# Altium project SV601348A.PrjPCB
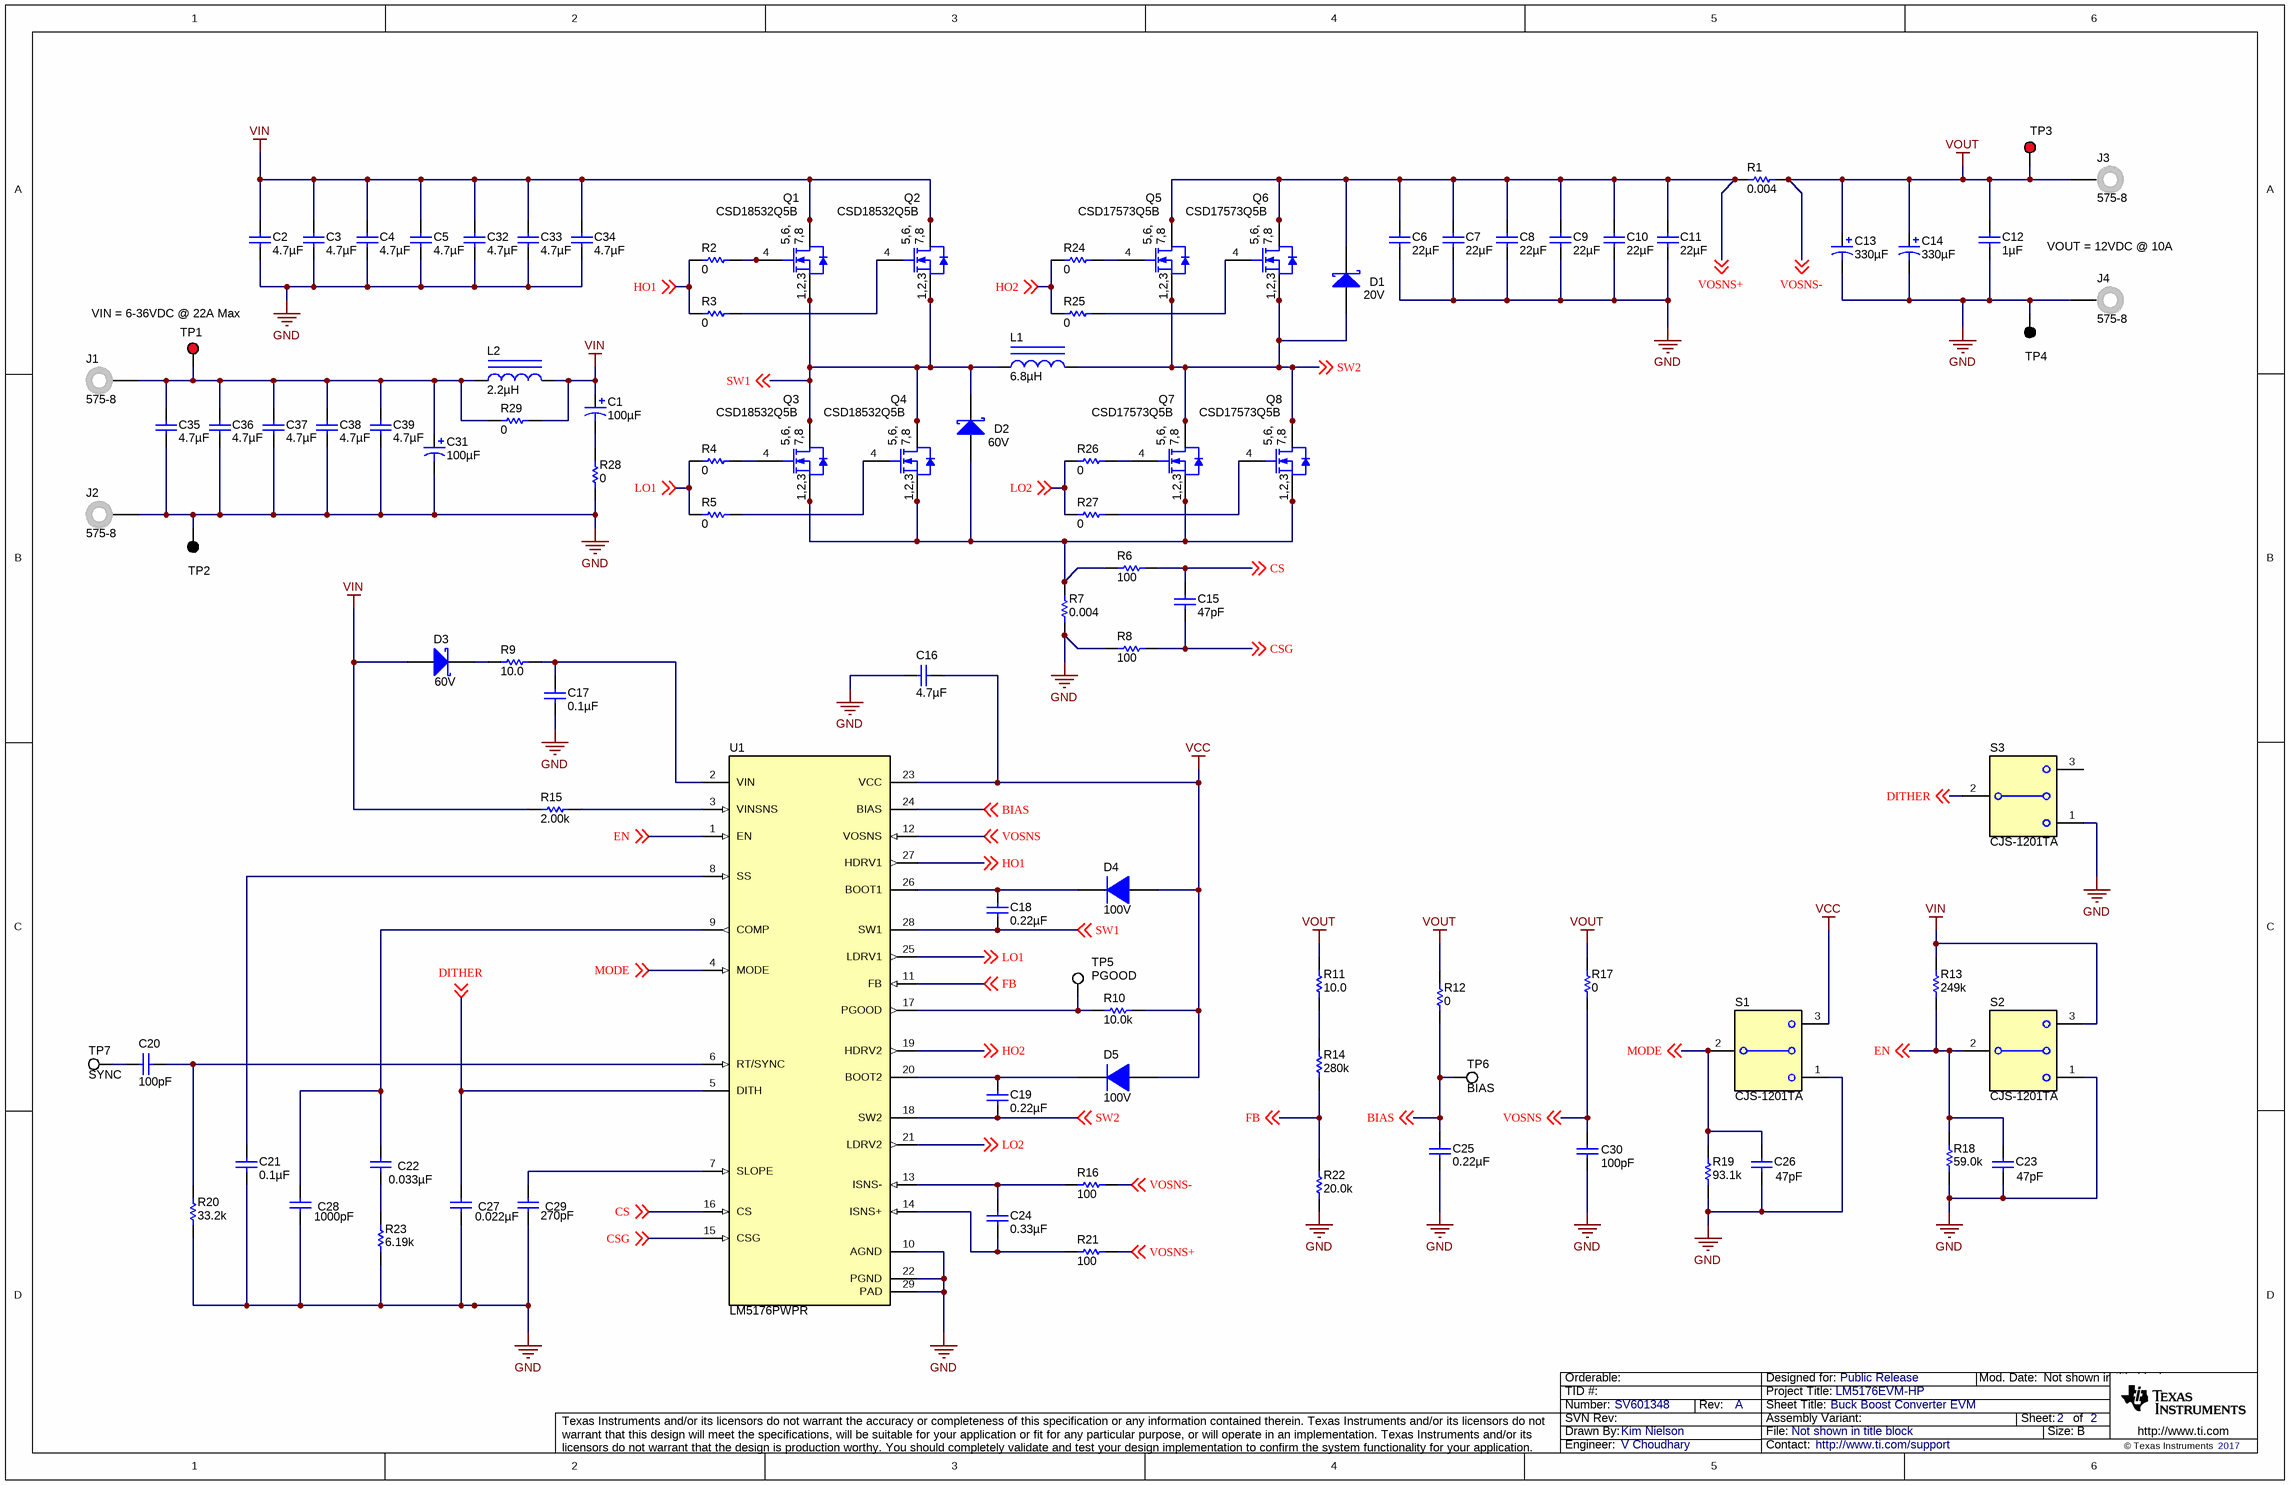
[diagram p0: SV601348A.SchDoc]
CopyrightYear: 2017; PCB_Layout: K Nielson; PCB_Rev: A; PRJ_Customer: Public Release; PRJ_Engineer: V Choudhary; PRJ_Number: SV601348; PRJ_Title: LM5176EVM-HP; SCH_Rev: A; TechSupport: http://www.ti.com/support
2 sheets, 125 parts. Net scope: global (net labels, ports and power ports of the same name join across sheets).
Board file: SV601348A.PcbDoc
Sheets:
  SV601348A.SchDoc
  SV601348A-HW.SchDoc

## Sheet SV601348A.SchDoc: Buck Boost Converter EVM
size 431 x 279 mm; Date: Not shown in title block; ApprovedBy: Not shown in title block; CheckedBy: Not shown in title block; Author: Not shown in title block; CompanyName: Not shown in title block; DrawnBy: Kim Nielson; Engineer: Neil Gutierrez; Organization: Not shown in title block; Address1: Not shown in title block; Address2: Not shown in title block; Address3: Not shown in title block; Address4: Not shown in title block; DocumentNumber: 2; Revision: Use project parameter SCH_Rev; SheetNumber: 2; SheetTotal: 2; PageSetup: Record=PageOptions¦CenterHorizontal=True¦CenterVertical=True¦PrintScale=0.62¦XCorrection=1.00¦YCorrection=1.00¦PrintKind=0¦BorderSize=5000000¦LeftOffset=0¦BottomOffset=0¦Orientation=2¦PaperLength=1000¦PaperWidth=1000¦Scale=100¦PaperSource=15¦PrintQuality=600¦MediaType=1¦DitherType=10¦PaperKind=Letter¦PrintScaleMode=1

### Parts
C1  ValueDisplayed: 100µF  [CR_1000x1270]  (hidden comment: PCR1J101MCL1GS)
C2  ValueDisplayed: 4.7µF  [1210_270]  (hidden comment: GRM32ER71K475KE14L)
C3  ValueDisplayed: 4.7µF  [1210_270]  (hidden comment: GRM32ER71K475KE14L)
C4  ValueDisplayed: 4.7µF  [1210_270]  (hidden comment: GRM32ER71K475KE14L)
C5  ValueDisplayed: 4.7µF  [1210_270]  (hidden comment: GRM32ER71K475KE14L)
C6  ValueDisplayed: 22µF  [1210_270]  (hidden comment: GRM32ER71E226KE15L)
C7  ValueDisplayed: 22µF  [1210_270]  (hidden comment: GRM32ER71E226KE15L)
C8  ValueDisplayed: 22µF  [1210_270]  (hidden comment: GRM32ER71E226KE15L)
C9  ValueDisplayed: 22µF  [1210_270]  (hidden comment: GRM32ER71E226KE15L)
C10  ValueDisplayed: 22µF  [1210_270]  (hidden comment: GRM32ER71E226KE15L)
C11  ValueDisplayed: 22µF  [1210_270]  (hidden comment: GRM32ER71E226KE15L)
C12  ValueDisplayed: 1µF  [0805_HV]  (hidden comment: GRM219R71E105KA88D)
C13  ValueDisplayed: 330µF  [SM_RADIAL_10AMM]  (hidden comment: 16SVP330M)
C14  ValueDisplayed: 330µF  [SM_RADIAL_10AMM]  (hidden comment: 16SVP330M)
C15  ValueDisplayed: 47pF  [0603L]  (hidden comment: GRM1885C1H470JA01D)
C16  ValueDisplayed: 4.7µF  [0805_HV]  (hidden comment: GRM21BR71C475KA73L)
C17  ValueDisplayed: 0.1µF  [0603L]  (hidden comment: GRM188R72A104KA35D)
C18  ValueDisplayed: 0.22µF  [0603L]  (hidden comment: GRM188R71E224KA88D)
C19  ValueDisplayed: 0.22µF  [0603L]  (hidden comment: GRM188R71E224KA88D)
C20  ValueDisplayed: 100pF  [0603L]  (hidden comment: GRM1885C2A101JA01D)
C21  ValueDisplayed: 0.1µF  [0603L]  (hidden comment: GRM188R72A104KA35D)
C22  ValueDisplayed: 0.033µF  [0603L]  (hidden comment: GRM188R71H333KA61D)
C23  47pF  [0603L]
C24  ValueDisplayed: 0.33µF  [0603L]  (hidden comment: GRM188R71C334KA01D)
C25  ValueDisplayed: 0.22µF  [0603]  (hidden comment: GRM188R71E224KA88D)
C26  47pF  [0603L]
C27  ValueDisplayed: 0.022µF  [0603L]  (hidden comment: C0603C223K5RACTU)
C28  ValueDisplayed: 1000pF  [0603L]  (hidden comment: GRM1885C2A102JA01D)
C29  ValueDisplayed: 270pF  [0603L]  (hidden comment: GRM1885C1H271JA01D)
C30  ValueDisplayed: 100pF  [0603L]  (hidden comment: GRM1885C2A101JA01D)
C31  ValueDisplayed: 100µF  [CR_1000x1270]  (hidden comment: PCR1J101MCL1GS)
C32  ValueDisplayed: 4.7µF  [1210_270]  (hidden comment: GRM32ER71K475KE14L)
C33  ValueDisplayed: 4.7µF  [1210_270]  (hidden comment: GRM32ER71K475KE14L)
C34  ValueDisplayed: 4.7µF  [1210_270]  (hidden comment: GRM32ER71K475KE14L)
C35  ValueDisplayed: 4.7µF  [1210_270]  (hidden comment: GRM32ER71K475KE14L)
C36  ValueDisplayed: 4.7µF  [1210_270]  (hidden comment: GRM32ER71K475KE14L)
C37  ValueDisplayed: 4.7µF  [1210_270]  (hidden comment: GRM32ER71K475KE14L)
C38  ValueDisplayed: 4.7µF  [1210_270]  (hidden comment: GRM32ER71K475KE14L)
C39  ValueDisplayed: 4.7µF  [1210_270]  (hidden comment: GRM32ER71K475KE14L)
D1  20V  [SMA]
D2  60V  [SMA]
D3  60V  [SOD-323F]
D4  100V  [sod-323]
D5  100V  [sod-323]
J1  575-8  [Keystone575-8]
J2  575-8  [Keystone575-8]
J3  575-8  [Keystone575-8]
J4  575-8  [Keystone575-8]
L1  ValueDisplayed: 6.8µH  [XAL1510]  (hidden comment: XAL1510-682MEB)
L2  ValueDisplayed: 2.2µH  [XAL1010]  (hidden comment: XAL1010-222MEB)
Q1  CSD18532Q5B  [DNK0008A]
Q2  CSD18532Q5B  [DNK0008A]
Q3  CSD18532Q5B  [DNK0008A]
Q4  CSD18532Q5B  [DNK0008A]
Q5  CSD17573Q5B  [DNK0008A]
Q6  CSD17573Q5B  [DNK0008A]
Q7  CSD17573Q5B  [DNK0008A]
Q8  CSD17573Q5B  [DNK0008A]
R1  ValueDisplayed: 0.004  [2512_WIDE]  (hidden comment: KRL6432E-M-R004-F-T1)
R2  value 0  [0603L]  (hidden comment: RC0603JR-070RL)
R3  value 0  [0603L]  (hidden comment: RC0603JR-070RL)
R4  value 0  [0603L]  (hidden comment: RC0603JR-070RL)
R5  value 0  [0603L]  (hidden comment: RC0603JR-070RL)
R6  value 100  [0603_HV]  (hidden comment: RC0603FR-07100RL)
R7  ValueDisplayed: 0.004  [2512_WIDE]  (hidden comment: KRL6432E-M-R004-F-T1)
R8  value 100  [0603_HV]  (hidden comment: RC0603FR-07100RL)
R9  value 10.0  [0603L]  (hidden comment: RC0603FR-0710RL)
R10  value 10.0k  [0603L]  (hidden comment: RC0603FR-0710KL)
R11  value 10.0  [0603L]  (hidden comment: RC0603FR-0710RL)
R12  value 0  [0603L]  (hidden comment: RC0603JR-070RL)
R13  value 249k  [0603L]  (hidden comment: RC0603FR-07249KL)
R14  value 280k  [0603L]  (hidden comment: RC0603FR-07280KL)
R15  ValueDisplayed: 2.00k  [0603]  (hidden comment: CRCW06032K00FKEA)
R16  100  [0603L]
R17  value 0  [0603L]  (hidden comment: RC0603JR-070RL)
R18  value 59.0k  [0603L]  (hidden comment: RC0603FR-0759KL)
R19  ValueDisplayed: 93.1k  [0603L]  (hidden comment: RC0603FR-0793K1L)
R20  ValueDisplayed: 33.2k  [0603L]  (hidden comment: CRCW060333K2FKEA)
R21  100  [0603L]
R22  value 20.0k  [0603L]  (hidden comment: RC0603FR-0720KL)
R23  ValueDisplayed: 6.19k  [0603L]  (hidden comment: CRCW06036K19FKEA)
R24  value 0  [0603L]  (hidden comment: RC0603JR-070RL)
R25  value 0  [0603L]  (hidden comment: RC0603JR-070RL)
R26  value 0  [0603L]  (hidden comment: RC0603JR-070RL)
R27  value 0  [0603L]  (hidden comment: RC0603JR-070RL)
R28  ValueDisplayed: 0  [1206]  (hidden comment: CRCW12060000Z0EA)
R29  ValueDisplayed: 0  [2512_WIDE_VISHAY]  (hidden comment: RCL12250000Z0EG)
S1  CJS-1201TA  [SW_CJS_1201A]
S2  CJS-1201TA  [SW_CJS_1201A]
S3  CJS-1201TA  [SW_CJS_1201A]
TP1  5005  [Keystone5005]  (value not drawn)
TP2  5006  [Keystone5006]  (value not drawn)
TP3  5005  [Keystone5005]  (value not drawn)
TP4  5006  [Keystone5006]  (value not drawn)
TP5  PGOOD  [Keystone5007]
TP6  BIAS  [Keystone5007]
TP7  SYNC  [Keystone5007]
U1  LM5176PWPR  [PWP0028C_N]

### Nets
GND: C2.2 C3.2 C4.2 C5.2 C6.2 C7.2 C8.2 C9.2 C10.2 C11.2 C12.2 C13.2(-) C14.2(-) C16.1 C17.2 C21.2 C23.2 C25.2 C26.2 C27.2 C28.2 C29.2 C30.2 C31.2(-) C32.2 C33.2 C34.2 C35.2 C36.2 C37.2 C38.2 C39.2 J2.1 J4.1 R7.1 R8.2 R18.1 R19.1 R20.1 R22.1 R23.1 R28.1 S1.1 S2.1 S3.1 TP2.1 TP4.1 U1.10(AGND) U1.22(PGND) U1.29(PAD)
VCC: C16.2 D4.2(A) D5.2(A) R10.2 S1.3 U1.23(VCC)
VIN: C1.1(+) C2.1 C3.1 C4.1 C5.1 C32.1 C33.1 C34.1 D3.2(A) L2.2 Q1.5(D) Q1.6(D) Q1.7(D) Q1.8(D) Q1.9(D) Q2.5(D) Q2.6(D) Q2.7(D) Q2.8(D) Q2.9(D) R13.2 R15.2 R29.2 S2.3
VOUT: C12.1 C13.1(+) C14.1(+) J3.1 R1.2 R11.1 R12.1 R16.2 R17.1 TP3.1 ; off-sheet VOSNS-  [also labelled VOSNS-]
BIAS: C25.1 R12.2 TP6.1 U1.24(BIAS) ; off-sheet BIAS
CS: C15.1 R6.1 U1.16(CS) ; off-sheet CS
CSG: C15.2 R8.1 U1.15(CSG) ; off-sheet CSG
DITHER: C27.1 S3.2(COM) U1.5(DITH) ; off-sheet DITHER
EN: C23.1 R13.1 R18.2 S2.2(COM) U1.1(EN) ; off-sheet EN
FB: R14.1 R22.2 U1.11(FB) ; off-sheet FB
HO1: R2.2 R3.2 U1.27(HDRV1) ; off-sheet HO1
HO2: R24.2 R25.2 U1.19(HDRV2) ; off-sheet HO2
LO1: R4.2 R5.2 U1.25(LDRV1) ; off-sheet LO1
LO2: R26.2 R27.2 U1.21(LDRV2) ; off-sheet LO2
MODE: C26.1 R19.2 S1.2(COM) U1.4(MODE) ; off-sheet MODE
SW1: C18.1 D2.1(K) L1.1 Q1.1(S) Q1.2(S) Q1.3(S) Q2.1(S) Q2.2(S) Q2.3(S) Q3.5(D) Q3.6(D) Q3.7(D) Q3.8(D) Q3.9(D) Q4.5(D) Q4.6(D) Q4.7(D) Q4.8(D) Q4.9(D) U1.28(SW1) ; off-sheet SW1
SW2: C19.2 D1.2(A) L1.2 Q5.1(S) Q5.2(S) Q5.3(S) Q6.1(S) Q6.2(S) Q6.3(S) Q7.5(D) Q7.6(D) Q7.7(D) Q7.8(D) Q7.9(D) Q8.5(D) Q8.6(D) Q8.7(D) Q8.8(D) Q8.9(D) U1.18(SW2) ; off-sheet SW2
VOSNS: C30.1 R17.2 U1.12(VOSNS) ; off-sheet VOSNS
VOSNS+: C6.1 C7.1 C8.1 C9.1 C10.1 C11.1 D1.1(K) Q5.5(D) Q5.6(D) Q5.7(D) Q5.8(D) Q5.9(D) Q6.5(D) Q6.6(D) Q6.7(D) Q6.8(D) Q6.9(D) R1.1 R21.2 ; off-sheet VOSNS+
NetC1_2: C1.2(-) R28.2
NetC17_1: C17.1 R9.1 U1.2(VIN)
NetC18_2: C18.2 D4.1(K) U1.26(BOOT1)
NetC19_1: C19.1 D5.1(K) U1.20(BOOT2)
NetC20_1: C20.1 TP7.1
NetC20_2: C20.2 R20.2 U1.6(RT/SYNC)
NetC21_1: C21.1 U1.8(SS)
NetC22_1: C22.1 C28.1 U1.9(COMP)
NetC22_2: C22.2 R23.2
NetC24_1: C24.1 R16.1 U1.13(ISNS-)
NetC24_2: C24.2 R21.1 U1.14(ISNS+)
NetC29_1: C29.1 U1.7(SLOPE)
NetC31_1: C31.1(+) C35.1 C36.1 C37.1 C38.1 C39.1 J1.1 L2.1 R29.1 TP1.1
NetD2_2: D2.2(A) Q3.1(S) Q3.2(S) Q3.3(S) Q4.1(S) Q4.2(S) Q4.3(S) Q7.1(S) Q7.2(S) Q7.3(S) Q8.1(S) Q8.2(S) Q8.3(S) R6.2 R7.2
NetD3_1: D3.1(K) R9.2
NetQ1_4: Q1.4(G) R2.1
NetQ2_4: Q2.4(G) R3.1
NetQ3_4: Q3.4(G) R4.1
NetQ4_4: Q4.4(G) R5.1
NetQ5_4: Q5.4(G) R24.1
NetQ6_4: Q6.4(G) R25.1
NetQ7_4: Q7.4(G) R26.1
NetQ8_4: Q8.4(G) R27.1
NetR10_1: R10.1 TP5.1 U1.17(PGOOD)
NetR11_2: R11.2 R14.2
NetR15_1: R15.1 U1.3(VINSNS)

Not connected (* = marked no-connect by the designer): S3 3

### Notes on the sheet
- VOUT = 12VDC @ 10A
- (near TP1) VIN = 6-36VDC @ 22A Max

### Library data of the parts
C1 C31 = PCR1J101MCL1GS: CAP, Aluminum Polymer, 100 µF, 63 V, +/- 20%, 0.024 ohm, SMD, 2-Leads, Dia 10.5mm, Pin Spacing 8mm SMD; Manufacturer: Nichicon; Polarized: Y; CompType: Capacitor; Value: 100uF; U/M: EA; Cap_F: 0.0001; Tolerance_%: 20; VDC_V: 63; Value2: 63V; ESR_ohm: 0.024; IRMS_A: 3; TaMin_C: -55; TaMax_C: 125; Cap_Case: 10x12.7mm; AEC Category: Q200; AEC Qualified: N
C2-C5 C32-C39 = GRM32ER71K475KE14L: CAP, CERM, 4.7 µF, 80 V, +/- 10%, X7R, 1210; Manufacturer: MuRata; CompType: Capacitor; Value: 4.7uF; U/M: EA; Tolerance_%: 10; VDC_V: 80; Polarized: N; Cap_F: 0.0000047; Value1: Unknown; Value2: 80V; TaMin_C: -55; TaMax_C: 125; Cap_Case: 1210; SizeArea_mm2: 8; SizeAreaWB_mm2: 14.7; SizeX_mm: 3.2; SizeY_mm: 2.5; SizeZ_mm: 2.7; AEC Category: Q200
C6-C11 = GRM32ER71E226KE15L: CAP, CERM, 22 µF, 25 V, +/- 10%, X7R, 1210; Manufacturer: MuRata; CompType: Capacitor; Value: 22uF; U/M: EA; Tolerance_%: 10; VDC_V: 25; Polarized: N; Cap_F: 0.000022; Value1: Unknown; Value2: 25V; TaMin_C: -55; TaMax_C: 125; Cap_Case: 1210; SizeArea_mm2: 8; SizeAreaWB_mm2: 14.7; SizeX_mm: 3.2; SizeY_mm: 2.5; SizeZ_mm: 2.7; AEC Category: Q200
C12 = GRM219R71E105KA88D: CAP, CERM, 1 µF, 25 V, +/- 10%, X7R, 0805; Manufacturer: MuRata; Polarized: N; CompType: Capacitor; Value: 1uF; U/M: EA; Cap_F: 0.000001; Tolerance_%: 10; Value1: Unknown; VDC_V: 25; Value2: 25V; TaMin_C: -55; TaMax_C: 125; Cap_Case: 0805
C13 C14 = 16SVP330M: CAP, OS-CON, 330 µF, 16 V, +/- 20%, 0.016 ohm, 10x10.3 SMD; Manufacturer: Sanyo; CompType: Capacitor; Value: 330uF; U/M: EA; Tolerance_%: 20; VDC_V: 16; ESR_ohm: 0.016; Polarized: Y; Cap_F: 0.00033; Value2: 16V; IRMS_A: 4.72; TaMin_C: -55; TaMax_C: 105; Cap_Case: 10.3x10.3x12.6
C15 C23 C26 = GRM1885C1H470JA01D: CAP, CERM, 47pF, 50V, +/-5%, C0G/NP0, 0603; Manufacturer: MuRata; Polarized: N; CompType: Capacitor; U/M: EA; Cap_F: 0.000000000047; Tolerance_%: 5; Value1: Unknown; VDC_V: 50; TaMin_C: -55; TaMax_C: 125; Cap_Case: 0603
C16 = GRM21BR71C475KA73L: CAP, CERM, 4.7 µF, 16 V, +/- 10%, X7R, 0805; Manufacturer: MuRata; Polarized: N; CompType: Capacitor; Value: 4.7uF; U/M: EA; Cap_F: 0.0000047; Tolerance_%: 10; ESR_ohm: 0.006; Value1: 0.006 ohm; VDC_V: 16; Value2: 16V; TaMin_C: -55; TaMax_C: 125; Cap_Case: 0805
C17 C21 = GRM188R72A104KA35D: CAP, CERM, 0.1uF, 100V, +/-10%, X7R, 0603; Manufacturer: MuRata; Polarized: N; CompType: Capacitor; U/M: EA; Cap_F: 0.0000001; Tolerance_%: 10; Value1: Unknown; VDC_V: 100; TaMin_C: -55; TaMax_C: 125; Cap_Case: 0603
C18 C19 = GRM188R71E224KA88D: CAP, CERM, 0.22 µF, 25 V, +/- 10%, X7R, 0603; Manufacturer: MuRata; Polarized: N; CompType: Capacitor; Value: 0.22uF; U/M: EA; Cap_F: 0.00000022; Tolerance_%: 10; Value1: Unknown; VDC_V: 25; Value2: 25V; TaMin_C: -55; TaMax_C: 125; Cap_Case: 0603
C20 C30 = GRM1885C2A101JA01D: CAP, CERM, 100pF, 100V, +/-5%, C0G/NP0, 0603; Manufacturer: MuRata; Polarized: N; CompType: Capacitor; U/M: EA; Cap_F: 0.0000000001; Tolerance_%: 5; Value1: Unknown; VDC_V: 100; TaMin_C: -55; TaMax_C: 125; Cap_Case: 0603
C22 = GRM188R71H333KA61D: CAP, CERM, 0.033 µF, 50 V, +/- 10%, X7R, 0603; Manufacturer: MuRata; Polarized: N; CompType: Capacitor; Value: 0.033uF; U/M: EA; Cap_F: 0.000000033; Tolerance_%: 10; Value1: Unknown; VDC_V: 50; Value2: 50V; TaMin_C: -55; TaMax_C: 125; Cap_Case: 0603; SizeArea_mm2: 1.28; SizeAreaWB_mm2: 4.68; SizeX_mm: 1.6; SizeY_mm: 0.8; SizeZ_mm: 1; AEC Category: Q200
C24 = GRM188R71C334KA01D: CAP, CERM, 0.33 µF, 16 V, +/- 10%, X7R, 0603; Manufacturer: MuRata; Polarized: N; CompType: Capacitor; Value: 0.33uF; U/M: EA; Cap_F: 0.00000033; Tolerance_%: 10; Value1: Unknown; VDC_V: 16; Value2: 16V; TaMin_C: -55; TaMax_C: 125; Cap_Case: 0603
C25 = GRM188R71E224KA88D: CAP, CERM, 0.22 µF, 25 V, +/- 10%, X7R, 0603; Manufacturer: MuRata; Polarized: N; CompType: Capacitor; Value: 0.22uF; U/M: EA; Cap_F: 0.00000022; Tolerance_%: 10; Value1: Unknown; VDC_V: 25; Value2: 25V; TaMin_C: -55; TaMax_C: 125
C27 = C0603C223K5RACTU: CAP, CERM, 0.022uF, 50V, +/-10%, X7R, 0603; Manufacturer: Kemet; Polarized: N; CompType: Capacitor; U/M: EA; Cap_F: 0.000000022; Tolerance_%: 10; Value1: Unknown; VDC_V: 50; TaMin_C: -55; TaMax_C: 125; Cap_Case: 0603
C28 = GRM1885C2A102JA01D: CAP, CERM, 1000 pF, 100 V, +/- 5%, C0G/NP0, 0603; Manufacturer: MuRata; Polarized: N; CompType: Capacitor; Value: 1000pF; U/M: EA; Cap_F: 0.000000001; Tolerance_%: 5; Value1: Unknown; VDC_V: 100; Value2: 100V; TaMin_C: -55; TaMax_C: 125; Cap_Case: 0603; SizeArea_mm2: 1.28; SizeAreaWB_mm2: 4.68; SizeX_mm: 1.6; SizeY_mm: 0.8; SizeZ_mm: 1; AEC Category: Q200
C29 = GRM1885C1H271JA01D: CAP, CERM, 270 pF, 50 V, +/- 5%, C0G/NP0, 0603; Manufacturer: MuRata; Polarized: N; CompType: Capacitor; Value: 270pF; U/M: EA; Cap_F: 0.00000000027; Tolerance_%: 5; Value1: Unknown; VDC_V: 50; Value2: 50V; TaMin_C: -55; TaMax_C: 125; Cap_Case: 0603; SizeArea_mm2: 1.28; SizeAreaWB_mm2: 4.68; SizeX_mm: 1.6; SizeY_mm: 0.8; SizeZ_mm: 1; AEC Category: Q200
D1 = RSX501L-20TE25: Diode, Schottky, 20 V, 5 A, SMA; Manufacturer: Rohm; U/M: EA; Vf_V: 0.39; Value1: 5A; Value2: 0.39V; Io_A: 5; Vr_V: 20; TJmax_C: 125
D2 = RB050L-60TE25: Diode, Schottky, 60 V, 3 A, SMA; Manufacturer: Rohm; U/M: EA; Vf_V: 0.56; Value1: 3A; Value2: 0.56V; Io_A: 3; Vr_V: 60; TJmax_C: 150
D3 = PMEG6010CEJ,115: Diode, Schottky, 60 V, 1 A, SOD-323F; Manufacturer: NXP Semiconductor; U/M: EA; Vf_V: 0.66; Value1: 1A; Value2: 0.66V; Io_A: 1; Vr_V: 60; TJmax_C: 150
D4 D5 = BAS316,115: Diode, Ultrafast, 100V, 0.25A, SOD-323; Manufacturer: NXP Semiconductor; U/M: EA; Vr_V: 100; Io_A: 0.25; Vf_V: 1.4; Value2: 1.4V; TJmax_C: 150
J1-J4 = 575-8: Standard Banana Jack, Uninsulated, 8.9mm; Manufacturer: Keystone; CompType: Connector
L1 = XAL1510-682MEB: Inductor, Shielded, Composite, 6.8 µH, 26 A, 0.00417 ohm, SMD; Manufacturer: Coilcraft; Value: 6.8uH; Ind_H: 6.8E-6; Imax_A: 26; Irms: 26A @ 40C rise; Isat: 36A @ 30% inductance drop; Value2: 26A; SizeAreaWB_mm2: 320.16; SizeArea_mm2: 252.56; SizeX_mm: 16.4; SizeY_mm: 15.4; SizeZ_mm: 10; AEC Category: Q200
L2 = XAL1010-222MEB: Inductor, Shielded, Composite, 2.2 µH, 32 A, 0.00255 ohm, SMD; Manufacturer: Coilcraft; Value: 2.2uH; Ind_H: 2.2E-6; Imax_A: 32; Irms: 32A @ 40C rise; Isat: 34A @ 30% inductance drop; Value2: 32A; SizeAreaWB_mm2: 159.6; SizeArea_mm2: 113; SizeX_mm: 11.3; SizeY_mm: 10; AEC Category: Q200
Q1-Q4 = CSD18532Q5B: MOSFET, N-CH, 60 V, 172 A, DNK0008A (VSON-CLIP-8); Manufacturer: Texas Instruments; Alternate Manufacturer: None; U/M: EA; ChType: N; Value: 60V; VdsMax_V: 60; Value1: 3.3 ohm; Rdson45_ohm: 3.3; Value2: 27 nC; QgTyp_nC: 27; Vgs_V: 1.6; IdsMax_A: 172; SizeAreaWB_mm2: 56; SizeArea_mm2: 30; SizeX_mm: 6; SizeY_mm: 5; SizeZ_mm: 1; AEC Category: Q101
Q5-Q8 = CSD17573Q5B: MOSFET, N-CH, 30 V, 100 A, DNK0008A (VSON-CLIP-8); Manufacturer: Texas Instruments; Alternate Manufacturer: None; U/M: EA; ChType: N; Value: 30V; VdsMax_V: 30; Value1: 0.00145 ohm; Rdson45_ohm: 0.00145; Value2: 49 nC; QgTyp_nC: 49; Vgs_V: 20; IdsMax_A: 100; SizeAreaWB_mm2: 56; SizeX_mm: 6; SizeY_mm: 5; SizeZ_mm: 1; AEC Category: Q101
R1 = KRL6432E-M-R004-F-T1: RES, 0.004, 1%, 3 W, 2512 WIDE; Manufacturer: Susumu Co Ltd; CompType: Resistor; U/M: EA; Value: 0.004; Power_W: 3; Tolerance_%: 1; TempCo: 50 ppm/C; Value_Code: 4L000; Value2: 3W; SizeArea_mm2: 20.16; SizeAreaWB_mm2: 43.16; SizeX_mm: 3.2; SizeY_mm: 6.3; SizeZ_mm: 0.7; AEC Category: Q200
R2-R5 R12 R17 R24-R27 = RC0603JR-070RL: RES, 0 ohm, 5%, 0.1W, 0603; Manufacturer: Yageo America; CompType: Resistor; Value_Code: 0000; Tolerance_%: 5; Power_W: 0.1; VDC_V: 50; TempCo: 200 ppm/C; EIA_Code: E24; U/M: EA
R6 R8 R16 R21 = RC0603FR-07100RL: RES, 100 ohm, 1%, 0.1W, 0603; Manufacturer: Yageo America; CompType: Resistor; Value_Code: 100R; Tolerance_%: 1; Power_W: 0.1; VDC_V: 150; TempCo: 200 ppm/C; EIA_Code: E96; U/M: EA
R7 = KRL6432E-M-R004-F-T1: RES, 0.004, 1%, 3 W, 2512 WIDE; Manufacturer: Susumu Co Ltd; CompType: Resistor; Value: 0.004; Tolerance_%: 1; Power_W: 3; TempCo: 50 ppm/C; U/M: EA; Value_Code: 4L000; Value2: 3W; SizeArea_mm2: 20.16; SizeAreaWB_mm2: 43.16; SizeX_mm: 3.2; SizeY_mm: 6.3; SizeZ_mm: 0.7; AEC Category: Q200
R9 R11 = RC0603FR-0710RL: RES, 10.0 ohm, 1%, 0.1W, 0603; Manufacturer: Yageo America; CompType: Resistor; Res_ohm: 10; Value_Code: 10R0; Tolerance_%: 1; Power_W: 0.1; VDC_V: 150; TempCo: 200 ppm/C; EIA_Code: E96; U/M: EA
R10 = RC0603FR-0710KL: RES, 10.0k ohm, 1%, 0.1W, 0603; Manufacturer: Yageo America; CompType: Resistor; Res_ohm: 10000; Value_Code: 10k0; Tolerance_%: 1; Power_W: 0.1; VDC_V: 150; TempCo: 200 ppm/C; EIA_Code: E96; U/M: EA
R13 = RC0603FR-07249KL: RES, 249k ohm, 1%, 0.1W, 0603; Manufacturer: Yageo America; CompType: Resistor; Res_ohm: 249000; Tolerance_%: 1; Power_W: 0.1; VDC_V: 150; TempCo: 200 ppm/C; EIA_Code: E96; U/M: EA
R14 = RC0603FR-07280KL: RES, 280k ohm, 1%, 0.1W, 0603; Manufacturer: Yageo America; CompType: Resistor; Res_ohm: 280000; Tolerance_%: 1; Power_W: 0.1; VDC_V: 150; TempCo: 200 ppm/C; EIA_Code: E96; U/M: EA
R15 = CRCW06032K00FKEA: RES, 2.00 k, 1%, 0.1 W, 0603; Manufacturer: Vishay-Dale; CompType: Resistor; Value: 2.00k; Res_ohm: 2000; Value_Code: 2k00; Tolerance_%: 1; Power_W: 0.1; Value2: 0.1W; VDC_V: 75; TempCo: 100 ppm/C; EIA_Code: E96; U/M: EA; SizeArea_mm2: 1.28; SizeX_mm: 1.6; SizeY_mm: 0.8; AEC Category: Q200
R18 = RC0603FR-0759KL: RES, 59.0k ohm, 1%, 0.1W, 0603; Manufacturer: Yageo America; CompType: Resistor; Res_ohm: 59000; Value_Code: 59k0; Tolerance_%: 1; Power_W: 0.1; VDC_V: 150; TempCo: 200 ppm/C; EIA_Code: E96; U/M: EA
R19 = RC0603FR-0793K1L: RES, 93.1 k, 1%, 0.1 W, 0603; Manufacturer: Yageo America; CompType: Resistor; Value: 93.1k; Res_ohm: 93100; Value_Code: 93k1; Tolerance_%: 1; Power_W: 0.1; Value2: 0.1W; VDC_V: 150; TempCo: 200 ppm/C; EIA_Code: E96; U/M: EA
R20 = CRCW060333K2FKEA: RES, 33.2 k, 1%, 0.1 W, 0603; Manufacturer: Vishay-Dale; CompType: Resistor; Value: 33.2k; Res_ohm: 33200; Value_Code: 33k2; Tolerance_%: 1; Power_W: 0.1; Value2: 0.1W; VDC_V: 75; TempCo: 100 ppm/C; EIA_Code: E96; U/M: EA; SizeArea_mm2: 1.28; SizeX_mm: 1.6; SizeY_mm: 0.8; AEC Category: Q200
R22 = RC0603FR-0720KL: RES, 20.0k ohm, 1%, 0.1W, 0603; Manufacturer: Yageo America; CompType: Resistor; Res_ohm: 20000; Value_Code: 20k0; Tolerance_%: 1; Power_W: 0.1; VDC_V: 150; TempCo: 200 ppm/C; EIA_Code: E96; U/M: EA
R23 = CRCW06036K19FKEA: RES, 6.19 k, 1%, 0.1 W, 0603; Manufacturer: Vishay-Dale; CompType: Resistor; Value: 6.19k; Res_ohm: 6190; Value_Code: 6k19; Tolerance_%: 1; Power_W: 0.1; Value2: 0.1W; VDC_V: 75; TempCo: 100 ppm/C; EIA_Code: E96; U/M: EA; SizeArea_mm2: 1.28; SizeX_mm: 1.6; SizeY_mm: 0.8; AEC Category: Q200
R28 = CRCW12060000Z0EA: RES, 0, 5%, 0.25 W, 1206; Manufacturer: Vishay-Dale; CompType: Resistor; Value: 0; Value_Code: 0000; Tolerance_%: 5; Power_W: 0.25; Value2: 0.25W; VDC_V: 200; TempCo: 200 ppm/C; SizeArea_mm2: 5.12; SizeX_mm: 3.2; SizeY_mm: 1.6; SizeZ_mm: 1.35; EIA_Code: E24; U/M: EA; AEC Category: Q200
R29 = RCL12250000Z0EG: RES, 0, 5%, 2 W, 2512 WIDE; Manufacturer: Vishay Draloric; CompType: Resistor; Value: 0; Value_Code: 0000; Tolerance_%: 5; Power_W: 2; Value2: 2W; TempCo: ppm/C; EIA_Code: E24; U/M: EA; AEC Category: Q200
S1-S3 = CJS-1201TA: Slide SW, SPDT 0.1A 50VDC; Manufacturer: Copal Electronics; SymbolCreator: a0799628; VDC_V: 50; SwitchFunction: On-Off-On; PositionCount: 1; CurrentRating_mA: 100; CompType: Switch
TP1 TP3 = 5005: Test Point, Compact, Red, TH; Manufacturer: Keystone; CompType: Test Point Loop; U/M: EA
TP2 TP4 = 5006: Test Point, Compact, Black, TH; Manufacturer: Keystone; CompType: Test Point Loop; U/M: EA
TP5-TP7 = 5007: Test Point, Compact, White, TH; Manufacturer: Keystone; CompType: Test Point Loop; U/M: EA
U1 = LM5176PWPR: 55 V Wide VIN Synchronous 4-Switch Buck-Boost Controller, PWP0028C (TSSOP-28); Alternate PartNumber: LM5176PWPT; Manufacturer: Texas Instruments; SymbolCreator: a0411947; SizeArea_mm2: 62.08; SizeAreaWB_mm2: 98.28; SizeX_mm: 6.4; SizeY_mm: 9.7; SizeZ_mm: 1.2; CompType: IC; U/M: EA

## Sheet SV601348A-HW.SchDoc: LM5176EVM-HP HARDWARE
size 431 x 279 mm; Date: Not shown in title block; ApprovedBy: Not shown in title block; CheckedBy: Not shown in title block; Author: Not shown in title block; CompanyName: Not shown in title block; DrawnBy: K Nielson; Engineer: Not shown in title block; Organization: Not shown in title block; Address1: Not shown in title block; Address2: Not shown in title block; Address3: Not shown in title block; Address4: Not shown in title block; DocumentNumber: 1; Revision: Use project parameter SCH_Rev; SheetNumber: 1; SheetTotal: 2; PageSetup: Record=PageOptions¦CenterHorizontal=True¦CenterVertical=True¦PrintScale=1.00¦XCorrection=1.00¦YCorrection=1.00¦PrintKind=0¦BorderSize=5000000¦LeftOffset=0¦BottomOffset=0¦Orientation=2¦PaperLength=1000¦PaperWidth=1000¦Scale=100¦PaperSource=15¦PrintQuality=600¦MediaType=1¦DitherType=10¦PaperKind=Letter¦PrintScaleMode=1
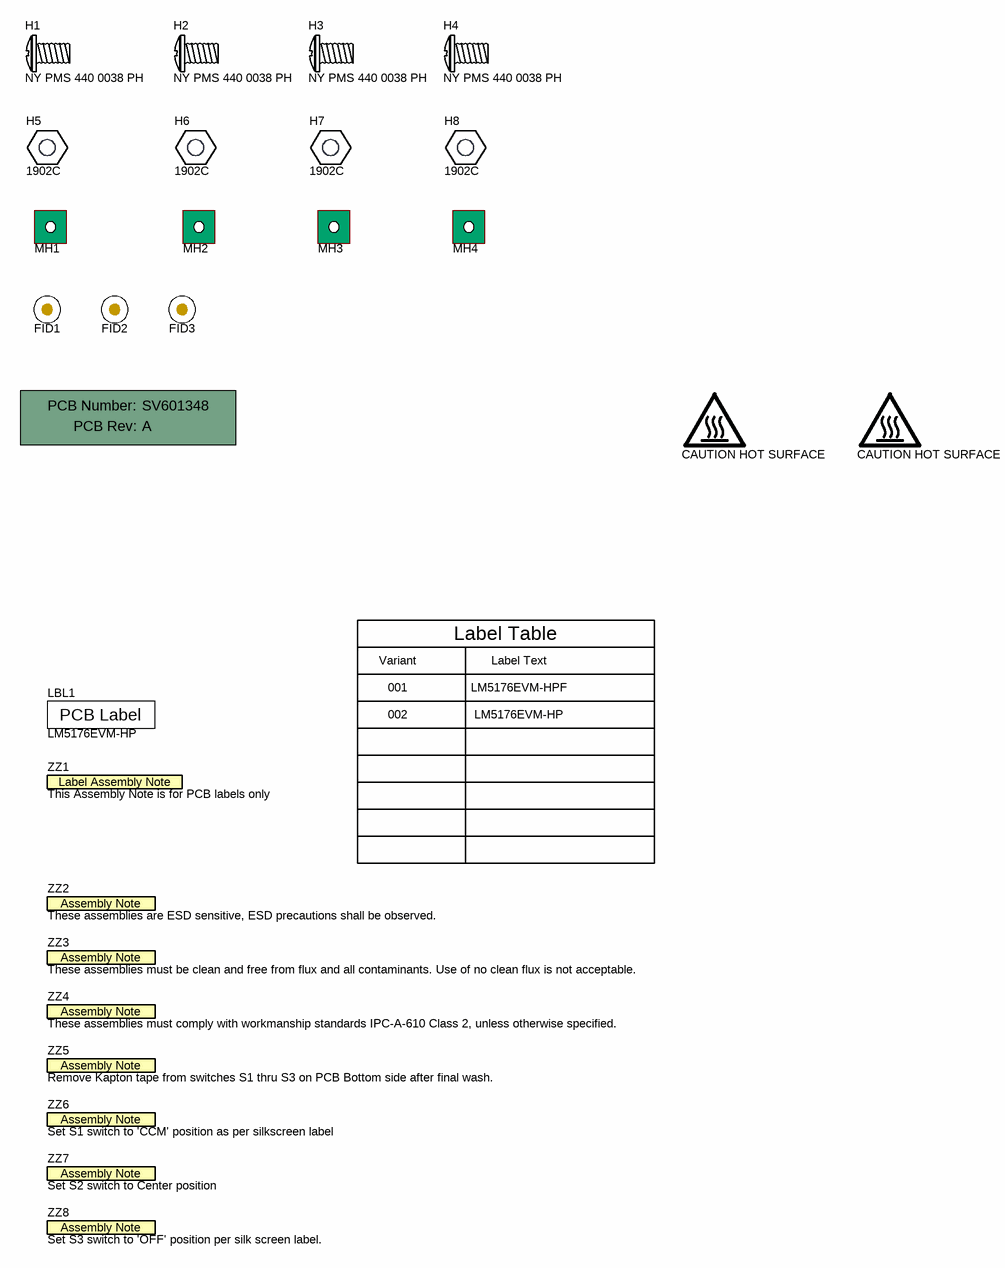
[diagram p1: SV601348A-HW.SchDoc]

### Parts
!PCB1  Printed Circuit Board  (value not drawn)  (mechanical)
FID1  Fiducial  [Fiducial10-20]  (value not drawn)
FID2  Fiducial  [Fiducial10-20]  (value not drawn)
FID3  Fiducial  [Fiducial10-20]  (value not drawn)
H1  NY PMS 440 0038 PH  (mechanical)
H2  NY PMS 440 0038 PH  (mechanical)
H3  NY PMS 440 0038 PH  (mechanical)
H4  NY PMS 440 0038 PH  (mechanical)
H5  1902C  [Keystone_1902C]
H6  1902C  [Keystone_1902C]
H7  1902C  [Keystone_1902C]
H8  1902C  [Keystone_1902C]
LBL1  LM5176EVM-HP  [Label_650x200]
LOGO4  CAUTION HOT SURFACE  [IEC_HotSurface_Small]  (no BOM)
LOGO5  CAUTION HOT SURFACE  [IEC_HotSurface_Small]  (no BOM)
MH1  MTG_NoPads  [MTG_159mil]  (value not drawn)  (no BOM)
MH2  MTG_NoPads  [MTG_159mil]  (value not drawn)  (no BOM)
MH3  MTG_NoPads  [MTG_159mil]  (value not drawn)  (no BOM)
MH4  MTG_NoPads  [MTG_159mil]  (value not drawn)  (no BOM)
ZZ1  This Assembly Note is for PCB labels only  [AssemblyNoteLabel]  (no BOM)
ZZ2  These assemblies are ESD sensitive, ESD precautions shall be observed.  [AssemblyNote]  (no BOM)
ZZ3  These assemblies must be clean and free from flux and all contaminants. Use of no clean flux is not acceptable.  [AssemblyNote]  (no BOM)
ZZ4  These assemblies must comply with workmanship standards IPC-A-610 Class 2, unless otherwise specified.  [AssemblyNote]  (no BOM)
ZZ5  Remove Kapton tape from switches S1 thru S3 on PCB Bottom side after final wash.  [AssemblyNote]  (no BOM)
ZZ6  Set S1 switch to 'CCM' position as per silkscreen label  [AssemblyNote]  (no BOM)
ZZ7  Set S2 switch to Center position  [AssemblyNote]  (no BOM)
ZZ8  Set S3 switch to 'OFF' position per silk screen label.  [AssemblyNote]  (no BOM)

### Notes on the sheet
- Variant
- Label Table
- Label Text
- 001
- 002
- LM5176EVM-HPF
- LM5176EVM-HP

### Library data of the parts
!PCB1 = PCB: Manufacturer: Any; PartNumber: SV601348; SymbolCreator: a0412235
FID1-FID3 = Fiducial: Fiducial mark.  There is nothing to buy or mount.; SymbolCreator: codlsc
H1-H4 = NY PMS 440 0038 PH: Screw, Pan Head , 4-40, 3/8", Nylon; Manufacturer: B&F Fastener Supply; SymbolCreator: a0412235; CompType: Hardware
H5-H8 = 1902C: Standoff, Hex, 0.5"L #4-40 Nylon; Manufacturer: Keystone; CompType: Hardware; SymbolCreator: a0412235
LBL1 = THT-14-423-10: Thermal Transfer Printable Labels, 0.650" W x 0.200" H - 10,000 per roll; Manufacturer: Brady; SymbolCreator: a0412235; CompType: Label; Note: Size: 0.65" x 0.20 "
LOGO4 LOGO5 = IEC_HotSurface: IEC 61010-1 Hot Surface Warning; SymbolCreator: a0412235
MH1-MH4 = Mounting Hole (non-standard) No Pad: PCB Mounting Hole, No Pad; Manufacturer: Any; SymbolCreator: a0412235
ZZ1 = AssemblyNoteLabel: SymbolCreator: a0412235
ZZ2-ZZ8 = AssemblyNote: SymbolCreator: codlsc

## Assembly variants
001: not fitted C23 C26 D1 D2 FID1 FID2 FID3 Q4 Q6 Q8 R29
002: not fitted C23 C26 C31 C35 C36 C37 C38 C39 D1 D2 FID1 FID2 FID3 L2 Q4 Q6 Q8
